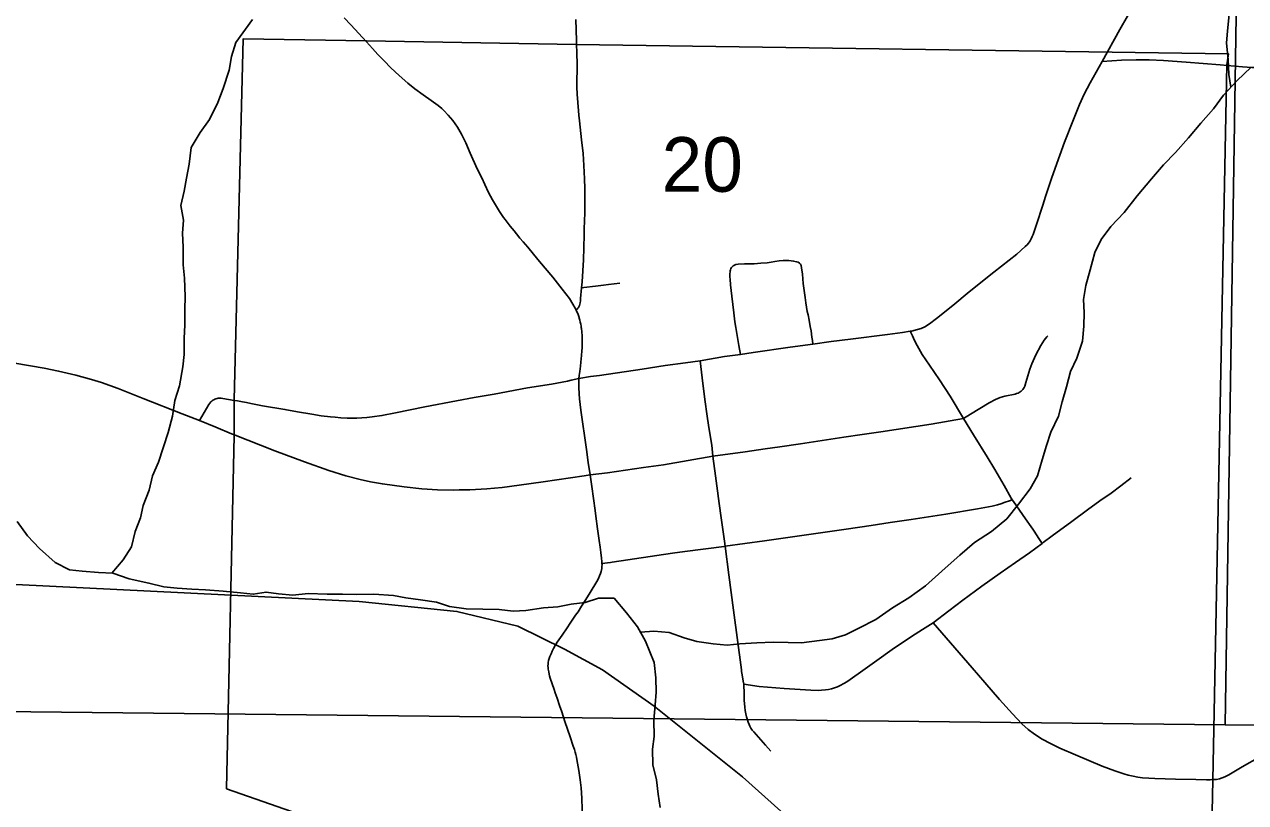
# Model space of a CAD drawing. Extents: x 0 to 34, y -8.9 to 22.
# Drawn here: x 24.831 to 25.767, y 12.889 to 13.486 of the extents above; entities that cross this region are included whole.
import ezdxf

# ---------------------------------------------------------------- set-up
doc = ezdxf.new("R2010")
doc.units = 0
for name, color, linetype in [('GM_X_City_Street', 7, 'Continuous'), ('GM_X_Corporation', 7, 'Continuous'), ('GM_X_County_Road', 7, 'Continuous'), ('GM_X_Minor_River', 7, 'Continuous'), ('GM_X_Rail_Line', 7, 'Continuous'), ('GM_X_Section_Text', 7, 'Continuous'), ('GM_X_State_Route', 7, 'Continuous'), ('GM_X_Township_Road', 7, 'Continuous')]:
    doc.layers.add(name, color=color, linetype=linetype)

msp = doc.modelspace()

# ---------------------------------------------------------------- linework, layer by layer
at = {"layer": 'GM_X_City_Street'}
for points in [[(25.25405, 13.26669), (25.25488, 13.26763), (25.25537, 13.26826), (25.25578, 13.26884), (25.25614, 13.26936), (25.2567, 13.27042), (25.257, 13.27131), (25.25715, 13.27231), (25.25735, 13.27383), (25.25751, 13.27562), (25.2582, 13.28379), (25.25859, 13.28836), (25.25969, 13.30534), (25.26004, 13.3144), (25.26023, 13.32472), (25.26028, 13.32898), (25.26062, 13.34124), (25.26085, 13.35158), (25.26074, 13.36009), (25.26038, 13.3674), (25.2599, 13.37773), (25.25942, 13.38686), (25.25816, 13.39724), (25.25659, 13.41191), (25.25611, 13.41615), (25.25516, 13.42911), (25.2549, 13.43211), (25.25484, 13.43277), (25.25469, 13.43711), (25.25468, 13.44455), (25.2548, 13.44945), (25.25487, 13.4525), (25.2549, 13.45492), (25.25478, 13.45834), (25.25473, 13.46065), (25.25461, 13.463), (25.25454, 13.46471), (25.25437, 13.46992)], [(25.34922, 13.22802), (25.3678, 13.23115), (25.38003, 13.23284), (25.38991, 13.23435), (25.4182, 13.23833), (25.43565, 13.24074), (25.44959, 13.24266), (25.46437, 13.24457), (25.4927, 13.24816), (25.50437, 13.24973), (25.51007, 13.25062), (25.51107, 13.25077), (25.51585, 13.25181), (25.5187, 13.25274), (25.5214, 13.25402), (25.525, 13.25627), (25.53042, 13.2603), (25.54296, 13.27044), (25.55545, 13.28068), (25.57433, 13.29591), (25.59182, 13.30978), (25.59835, 13.31545), (25.59972, 13.31677), (25.60081, 13.31805), (25.60155, 13.31903), (25.60216, 13.32), (25.60292, 13.32148), (25.60372, 13.32314), (25.60436, 13.32475), (25.6071, 13.33248), (25.61179, 13.34726), (25.61396, 13.35373), (25.61881, 13.3685), (25.62484, 13.38548), (25.62859, 13.39537), (25.63526, 13.41279), (25.63996, 13.42432), (25.64362, 13.43224), (25.64822, 13.44107), (25.65731, 13.45741)], [(25.65731, 13.45741), (25.67222, 13.45827), (25.68341, 13.45868), (25.69333, 13.4586), (25.70448, 13.45804), (25.72178, 13.45679), (25.74775, 13.45469), (25.75322, 13.4542)], [(25.38003, 13.23284), (25.37887, 13.23957), (25.37649, 13.25339), (25.37585, 13.25792), (25.37488, 13.26483), (25.37334, 13.2775), (25.37238, 13.28626), (25.37206, 13.29055), (25.37202, 13.29215), (25.37201, 13.29373), (25.372, 13.29484), (25.37211, 13.29599), (25.37225, 13.29687), (25.37246, 13.29771), (25.37277, 13.29857), (25.37327, 13.29942), (25.37383, 13.30013), (25.37447, 13.30069), (25.37544, 13.30131), (25.37652, 13.30168), (25.37831, 13.30192), (25.38322, 13.30213), (25.39067, 13.30236), (25.3956, 13.30273), (25.40056, 13.30311), (25.40362, 13.30354), (25.40637, 13.30401), (25.40966, 13.30449), (25.41275, 13.30469), (25.41709, 13.30469), (25.42073, 13.30434), (25.42309, 13.30385), (25.42421, 13.30342), (25.42519, 13.30278), (25.42597, 13.30192), (25.42651, 13.3009), (25.42692, 13.2992), (25.42752, 13.29427), (25.42815, 13.28724), (25.4296, 13.27651), (25.43028, 13.27224), (25.43075, 13.26916), (25.43127, 13.26578), (25.43184, 13.26307), (25.43268, 13.25911), (25.43356, 13.25411), (25.43414, 13.25088), (25.43486, 13.24604), (25.43523, 13.24359), (25.43565, 13.24074)], [(25.2582, 13.28379), (25.25992, 13.284), (25.269, 13.28513), (25.27516, 13.28588), (25.27883, 13.28636), (25.28315, 13.2869), (25.28759, 13.28741)], [(25.6113, 13.08805), (25.60889, 13.09173), (25.60523, 13.09735), (25.60419, 13.09881), (25.60282, 13.10082), (25.59864, 13.10694), (25.59396, 13.1135), (25.5893, 13.12005), (25.58832, 13.12153), (25.58758, 13.12264), (25.58221, 13.13241), (25.57504, 13.14475), (25.56922, 13.15427), (25.5588, 13.17117), (25.5511, 13.18381), (25.54071, 13.20084), (25.5326, 13.21333), (25.52489, 13.22459), (25.51947, 13.23287), (25.5154, 13.23977), (25.5135, 13.24363), (25.51181, 13.24707), (25.51007, 13.25062)], [(25.5511, 13.18381), (25.55629, 13.18697), (25.57063, 13.19575), (25.57558, 13.19835), (25.57903, 13.19977), (25.58261, 13.20081), (25.59055, 13.20244), (25.59175, 13.20281), (25.5929, 13.20326), (25.59381, 13.20371), (25.59453, 13.20416), (25.59529, 13.20478), (25.59593, 13.20538), (25.59647, 13.20606), (25.59709, 13.20683), (25.59755, 13.20757), (25.59795, 13.20847), (25.59894, 13.21143), (25.60183, 13.22161), (25.60343, 13.22574), (25.60638, 13.2325), (25.6102, 13.23963), (25.61288, 13.24382), (25.61486, 13.24622), (25.61573, 13.2471)], [(24.992, 13.19759), (24.99456, 13.19718), (24.99827, 13.19654), (25.00133, 13.19597), (25.00462, 13.19531), (25.01366, 13.19349), (25.03081, 13.19067), (25.04056, 13.18876), (25.05157, 13.18696), (25.05848, 13.18587), (25.06565, 13.18498), (25.06936, 13.18463), (25.07368, 13.18433), (25.07846, 13.18409), (25.08296, 13.184), (25.08607, 13.18399), (25.08978, 13.1842), (25.09354, 13.18443), (25.09783, 13.18492), (25.1052, 13.18599), (25.11555, 13.18798), (25.13804, 13.19261), (25.16244, 13.19732), (25.17586, 13.19976), (25.19116, 13.20234), (25.21681, 13.20713), (25.23521, 13.21012), (25.24735, 13.21238), (25.25037, 13.21302), (25.25626, 13.21441), (25.26511, 13.21587), (25.27207, 13.21679), (25.30461, 13.22162), (25.32241, 13.22445), (25.33779, 13.22649), (25.34922, 13.22802)], [(25.35892, 13.15479), (25.35799, 13.16321), (25.35589, 13.17673), (25.35435, 13.18721), (25.35306, 13.19646), (25.35127, 13.21061), (25.34922, 13.22802)], [(25.35892, 13.15479), (25.38371, 13.15809), (25.39906, 13.16054), (25.41013, 13.16211), (25.42613, 13.16439), (25.45935, 13.16931), (25.47347, 13.17152), (25.48761, 13.1736), (25.52633, 13.17946), (25.5511, 13.18381)], [(25.52779, 13.02712), (25.53979, 13.03626), (25.55064, 13.04451), (25.56511, 13.05518), (25.57924, 13.06528), (25.591, 13.07338), (25.60173, 13.08074), (25.6113, 13.08805), (25.61209, 13.08865), (25.619, 13.09389), (25.63403, 13.10487), (25.64604, 13.11368), (25.65561, 13.12054), (25.66426, 13.12651), (25.67169, 13.13201), (25.67945, 13.13816)], [(25.27387, 13.07253), (25.28034, 13.07349), (25.28157, 13.07367), (25.32801, 13.08042), (25.33745, 13.08179), (25.36762, 13.08575), (25.36835, 13.08585), (25.39839, 13.09008), (25.42168, 13.0934), (25.46107, 13.09901), (25.48015, 13.10179), (25.49489, 13.10395), (25.51084, 13.10643), (25.53755, 13.11044), (25.56177, 13.11456), (25.57304, 13.11667), (25.57712, 13.11759), (25.57953, 13.11826), (25.58295, 13.11949), (25.58624, 13.12069), (25.58832, 13.12153)], [(25.40332, 12.9287), (25.39918, 12.93328), (25.39022, 12.94351), (25.38908, 12.94499), (25.38808, 12.94654), (25.38726, 12.94793), (25.38663, 12.94926), (25.38583, 12.95115), (25.38532, 12.95272), (25.38464, 12.95511), (25.38412, 12.95753), (25.38369, 12.95991), (25.38337, 12.96241), (25.38289, 12.96786), (25.38285, 12.97268), (25.38268, 12.98015)]]:
    msp.add_lwpolyline(points, dxfattribs=at)
at = {"layer": 'GM_X_Corporation'}
for points in [[(25.76644, 13.90401), (24.75016, 13.90401), (24.74203, 12.95998), (25.75175, 12.94901)], [(26.78167, 13.90401), (25.76644, 13.90401), (25.75175, 12.94901), (26.76637, 12.93923)], [(25.7365, 12.63831), (24.98605, 12.90005), (24.99203, 13.17065), (24.9918, 13.19813), (24.99876, 13.47456), (25.09326, 13.47304), (25.25417, 13.47045), (25.75419, 13.46323), (25.75301, 13.45473), (25.74226, 12.9065)]]:
    msp.add_lwpolyline(points, close=True, dxfattribs=at)
at = {"layer": 'GM_X_County_Road'}
msp.add_lwpolyline([(25.65731, 13.45741), (25.67092, 13.48194), (25.67681, 13.49213), (25.68178, 13.5), (25.68539, 13.50504), (25.68891, 13.50939), (25.6924, 13.51292), (25.69572, 13.51572), (25.70126, 13.51967), (25.70654, 13.52292), (25.71311, 13.52642), (25.72268, 13.53089), (25.74322, 13.53975), (25.76709, 13.55029), (25.80807, 13.56825)], dxfattribs=at)
at = {"layer": 'GM_X_Minor_River'}
for points in [[(25.7561, 13.4376), (25.75447, 13.44738), (25.75398, 13.45875), (25.75272, 13.47125), (25.75338, 13.48075), (25.75477, 13.49328)], [(24.89814, 13.0652), (24.90676, 13.07551), (24.91309, 13.08545), (24.916, 13.09725), (24.92006, 13.10754), (24.92223, 13.11706), (24.92666, 13.12887), (24.9292, 13.13991), (24.93401, 13.15021), (24.94135, 13.17307), (24.94463, 13.18563), (24.94641, 13.19741), (24.95008, 13.20884), (24.95258, 13.22329), (24.95362, 13.23279), (24.9535, 13.24493), (24.95415, 13.25556), (24.95403, 13.26732), (24.95431, 13.27719), (24.95379, 13.29121), (24.95293, 13.30145), (24.9528, 13.3151), (24.95231, 13.32572), (24.95297, 13.33559), (24.95097, 13.34695), (24.9535, 13.35798), (24.9553, 13.36787), (24.95746, 13.37852), (24.95885, 13.39143), (24.96592, 13.4029), (24.97301, 13.41286), (24.97932, 13.42584), (24.98337, 13.43651), (24.98815, 13.45061), (24.98993, 13.46126), (24.99323, 13.47192), (25.00592, 13.48953)], [(25.30343, 13.02005), (25.31372, 13.02074), (25.32546, 13.01975), (25.33686, 13.01572), (25.34672, 13.01281), (25.35923, 13.01107), (25.36983, 13.01007), (25.37966, 13.01095), (25.39252, 13.01187), (25.405, 13.01241), (25.41674, 13.01218), (25.42695, 13.01193), (25.44056, 13.01361), (25.45039, 13.01487), (25.46057, 13.01804), (25.47074, 13.0231), (25.48392, 13.02972), (25.49669, 13.0386), (25.5091, 13.04634), (25.52188, 13.05561), (25.53688, 13.06908), (25.54813, 13.07908), (25.55939, 13.08871), (25.57255, 13.09722), (25.58418, 13.10685), (25.59315, 13.11797), (25.60211, 13.12984), (25.60769, 13.13977), (25.61135, 13.15196), (25.61465, 13.163), (25.61795, 13.17329), (25.62389, 13.1855), (25.6268, 13.19654), (25.63009, 13.20796), (25.633, 13.21976), (25.63782, 13.23006), (25.64223, 13.24302), (25.64325, 13.25441), (25.64352, 13.26504), (25.64305, 13.27489), (25.64483, 13.28554), (25.64812, 13.29772), (25.65177, 13.31104), (25.65659, 13.32097), (25.66406, 13.33092), (25.67417, 13.34167), (25.68426, 13.35432), (25.6951, 13.36735), (25.70446, 13.37809), (25.71344, 13.38768), (25.72355, 13.39881), (25.7329, 13.40993), (25.74262, 13.42105), (25.75047, 13.43139), (25.76057, 13.44252), (25.77144, 13.4529)], [(24.82548, 13.10482), (24.83354, 13.09392), (24.84272, 13.08417), (24.85456, 13.07332), (24.86559, 13.06777), (24.87544, 13.06676), (24.88793, 13.06578), (24.89892, 13.06516), (24.91145, 13.06077), (24.92661, 13.05755), (24.938, 13.05466), (24.94822, 13.05365), (24.95958, 13.05304), (24.96981, 13.05241), (24.98344, 13.05144), (24.9967, 13.0501), (25.00654, 13.04908), (25.01637, 13.05073), (25.02584, 13.04933), (25.03683, 13.04833), (25.04854, 13.04962), (25.06331, 13.04905), (25.07504, 13.0492), (25.08601, 13.04896), (25.09888, 13.04912), (25.11402, 13.04818), (25.1235, 13.0464), (25.13487, 13.04465), (25.147, 13.0429), (25.15687, 13.03962), (25.16975, 13.03788), (25.18262, 13.03767), (25.19511, 13.03744), (25.20572, 13.03606), (25.21556, 13.03657), (25.22916, 13.03864), (25.24012, 13.03953), (25.25032, 13.04156), (25.2609, 13.04283), (25.27109, 13.046), (25.28319, 13.04615), (25.29277, 13.03489), (25.3012, 13.02399), (25.30736, 13.01307), (25.31396, 12.99684), (25.31521, 12.98509), (25.31533, 12.97409), (25.31467, 12.96422), (25.31365, 12.95245), (25.31378, 12.93993), (25.31273, 12.93043), (25.31286, 12.91829), (25.31562, 12.90694), (25.31686, 12.89596), (25.31848, 12.88573)]]:
    msp.add_lwpolyline(points, dxfattribs=at)
at = {"layer": 'GM_X_Rail_Line'}
msp.add_lwpolyline([(23.71667, 13.1053), (23.72607, 13.1053), (24.56118, 13.06964), (25.08773, 13.04338), (25.16264, 13.03587), (25.20927, 13.02472), (25.24514, 13.00686), (25.27421, 12.99101), (25.31387, 12.96337), (25.38154, 12.90918), (25.44528, 12.85209), (25.48204, 12.82546), (25.52272, 12.80268), (25.57031, 12.7886), (25.63745, 12.78312), (25.75326, 12.77621), (26.26802, 12.73933), (26.76534, 12.71041), (26.8928, 12.70047), (26.96386, 12.69787)], dxfattribs=at)
at = {"layer": 'GM_X_State_Route'}
msp.add_line((25.3678, 13.08983), (25.36835, 13.08585), dxfattribs=at)
for points in [[(25.09346, 13.4725), (25.08125, 13.48535), (25.07612, 13.49081)], [(25.25689, 13.21965), (25.25739, 13.22375), (25.25775, 13.22681), (25.25798, 13.22944), (25.25823, 13.23203), (25.25846, 13.23555), (25.25857, 13.23798), (25.25874, 13.24138), (25.25878, 13.2431), (25.2587, 13.2454), (25.25858, 13.24783), (25.2585, 13.24935), (25.25837, 13.25093), (25.25826, 13.25185), (25.25815, 13.25269), (25.258, 13.25352), (25.25785, 13.25437), (25.25755, 13.25595), (25.25739, 13.25675), (25.25723, 13.25759), (25.25691, 13.25906), (25.25674, 13.25983), (25.25651, 13.26057), (25.25631, 13.26124), (25.25608, 13.26192), (25.25582, 13.26265), (25.25555, 13.26335), (25.25405, 13.26669), (25.25332, 13.26832), (25.25159, 13.27147), (25.24899, 13.27556), (25.24347, 13.28296), (25.23609, 13.29212), (25.22611, 13.30403), (25.22131, 13.30974), (25.21694, 13.31495), (25.21338, 13.31918), (25.21103, 13.32199), (25.20834, 13.32523), (25.20645, 13.32755), (25.20346, 13.33119), (25.19954, 13.33614), (25.19831, 13.33783), (25.19532, 13.3423), (25.19144, 13.34862), (25.18993, 13.35138), (25.18697, 13.35683), (25.18402, 13.36301), (25.18173, 13.36808), (25.17851, 13.37459), (25.17479, 13.38251), (25.17294, 13.38711), (25.16953, 13.39507), (25.16617, 13.40166), (25.16305, 13.40695), (25.15952, 13.41197), (25.15602, 13.41621), (25.15275, 13.41968), (25.15099, 13.42126), (25.14823, 13.42351), (25.14296, 13.42748), (25.13689, 13.43166), (25.13032, 13.43637), (25.12496, 13.44067), (25.11844, 13.44649), (25.11211, 13.4525), (25.10684, 13.45779), (25.10216, 13.46275), (25.09798, 13.46726), (25.09346, 13.4725)], [(24.80615, 13.22909), (24.80714, 13.22893), (24.82373, 13.22615), (24.84636, 13.22226), (24.85731, 13.22008), (24.87057, 13.21691), (24.8825, 13.21362), (24.89018, 13.2112), (24.90301, 13.20661), (24.92208, 13.19914), (24.95213, 13.18729), (24.96535, 13.18213), (24.97796, 13.17698), (24.98986, 13.17197), (24.99134, 13.17143)], [(25.25675, 13.19889), (25.25663, 13.19986), (25.25648, 13.20161), (25.25629, 13.2038), (25.25618, 13.20622), (25.25614, 13.20819), (25.25614, 13.21034), (25.2562, 13.21231), (25.25623, 13.21342), (25.25626, 13.21441), (25.25651, 13.21657), (25.25689, 13.21965)], [(25.27181, 13.09014), (25.27045, 13.09918), (25.26926, 13.10898), (25.2686, 13.11325), (25.26599, 13.13166), (25.26471, 13.14053), (25.26333, 13.15011), (25.262, 13.15995), (25.25779, 13.19011), (25.25675, 13.19889)], [(24.99134, 13.17143), (25.02297, 13.15885), (25.04571, 13.15044), (25.06453, 13.14396), (25.07762, 13.1399), (25.08846, 13.13699), (25.09638, 13.13523), (25.10559, 13.13364), (25.12225, 13.13136), (25.13587, 13.12992), (25.14769, 13.12919), (25.16015, 13.12892), (25.1643, 13.12898)], [(25.26471, 13.14053), (25.27801, 13.14198), (25.30565, 13.14615), (25.32103, 13.14826), (25.35892, 13.15479)], [(25.35892, 13.15479), (25.36088, 13.13984), (25.36193, 13.13219), (25.36378, 13.11869), (25.36529, 13.10771), (25.3678, 13.08983)], [(25.1643, 13.12898), (25.17261, 13.12911), (25.18567, 13.12982), (25.19746, 13.1309), (25.21041, 13.13261), (25.22887, 13.13523), (25.26022, 13.13987), (25.26471, 13.14053)], [(25.24383, 13.01844), (25.24662, 13.02254), (25.25004, 13.02778), (25.25362, 13.03294), (25.25551, 13.0357), (25.25813, 13.03985), (25.2615, 13.04515), (25.26482, 13.05048), (25.26998, 13.05879), (25.27116, 13.06107), (25.27211, 13.06317), (25.27278, 13.06483), (25.2733, 13.06645), (25.27373, 13.06873), (25.27387, 13.07021), (25.27392, 13.07174), (25.27387, 13.07253), (25.27379, 13.07423), (25.2736, 13.07659), (25.27313, 13.08101), (25.27256, 13.08512), (25.27181, 13.09014)], [(25.36835, 13.08585), (25.37124, 13.06397), (25.37473, 13.03683), (25.38072, 12.99118), (25.38087, 12.98991), (25.38104, 12.98868), (25.38128, 12.9872)], [(25.38268, 12.98015), (25.3944, 12.97838), (25.41363, 12.97671), (25.43411, 12.97554), (25.4398, 12.97537), (25.44229, 12.97548), (25.44512, 12.97577), (25.44755, 12.97618), (25.44985, 12.97667), (25.45145, 12.97708), (25.45288, 12.97757), (25.45454, 12.97811), (25.45602, 12.97877), (25.45977, 12.98079), (25.46242, 12.98249), (25.47561, 12.99183), (25.48467, 12.99836), (25.49628, 13.00667), (25.51118, 13.01672), (25.51954, 13.02201), (25.52779, 13.02712)], [(25.52779, 13.02712), (25.53449, 13.01945), (25.55764, 12.99276), (25.56741, 12.98155), (25.57871, 12.96841), (25.5885, 12.95733), (25.59573, 12.94985), (25.60073, 12.94538), (25.60557, 12.94171), (25.61122, 12.9381), (25.61766, 12.93456), (25.62485, 12.93107), (25.63677, 12.92598), (25.65731, 12.91744), (25.66703, 12.91362), (25.674, 12.91134), (25.67722, 12.91048), (25.68112, 12.90957), (25.68459, 12.90897), (25.68838, 12.90847), (25.693, 12.90805), (25.69759, 12.90779), (25.71368, 12.90734), (25.72917, 12.90699), (25.7372, 12.90691), (25.74012, 12.90692), (25.74154, 12.90697)], [(25.25896, 12.8754), (25.25848, 12.89275), (25.258, 12.90082), (25.25728, 12.90694), (25.25647, 12.91223), (25.25585, 12.91551), (25.25487, 12.92084), (25.25428, 12.92426), (25.25388, 12.92619), (25.25345, 12.92798), (25.25314, 12.92907), (25.25279, 12.93008), (25.25192, 12.93261), (25.24943, 12.93971), (25.2455, 12.95143), (25.24299, 12.95905), (25.24143, 12.96372), (25.23947, 12.96953), (25.23807, 12.97354), (25.23719, 12.97611), (25.23417, 12.98487), (25.23373, 12.98645), (25.23335, 12.98793), (25.23304, 12.98969), (25.23272, 12.99152), (25.23259, 12.99283), (25.2325, 12.99419), (25.23255, 12.99546), (25.23268, 12.99686), (25.23298, 12.99826), (25.23346, 12.99988), (25.23399, 13.00137), (25.23482, 13.00338), (25.23573, 13.00539), (25.23676, 13.00746), (25.23809, 13.00976), (25.23965, 13.01231), (25.24327, 13.01763), (25.24383, 13.01844)], [(25.38128, 12.9872), (25.38161, 12.9854), (25.38188, 12.98416), (25.38221, 12.98238), (25.38268, 12.98015)], [(25.74154, 12.90697), (25.74277, 12.90702), (25.74494, 12.9072), (25.74738, 12.90769), (25.74936, 12.90838), (25.75133, 12.90918), (25.75303, 12.90998), (25.75445, 12.91079), (25.76468, 12.91676), (25.77819, 12.92443)]]:
    msp.add_lwpolyline(points, dxfattribs=at)
at = {"layer": 'GM_X_Township_Road'}
for points in [[(25.25437, 13.46992), (25.25426, 13.47348), (25.25389, 13.48948)], [(25.75322, 13.4542), (25.76484, 13.45318), (25.77215, 13.45283), (25.77769, 13.45282), (25.78055, 13.453)], [(24.96535, 13.18213), (24.97244, 13.19456), (24.97324, 13.19559), (24.97406, 13.19646), (24.97478, 13.19711), (24.97549, 13.19766), (24.97627, 13.19815), (24.9771, 13.19857), (24.97791, 13.19887), (24.97887, 13.19915), (24.97967, 13.19928), (24.98071, 13.19935), (24.98187, 13.19931), (24.98321, 13.19916), (24.992, 13.19759)]]:
    msp.add_lwpolyline(points, dxfattribs=at)

# ---------------------------------------------------------------- texts
at = {"layer": 'GM_X_Section_Text'}
msp.add_text('20', height=0.041856, rotation=0.00001, dxfattribs=at).set_placement((25.31963, 13.35747))

doc.saveas('drawing.dxf')
